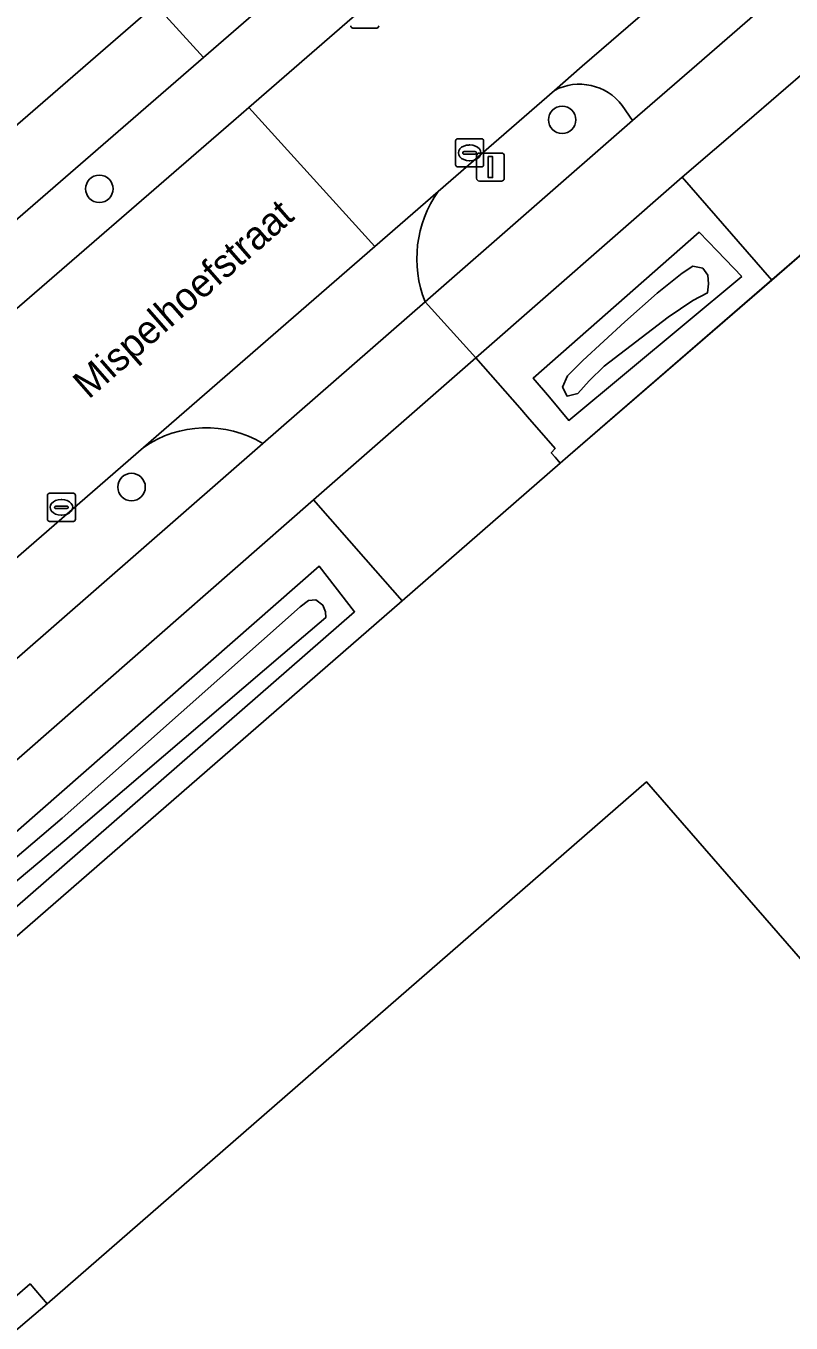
# Model space of a CAD drawing. Extents: x 156141 to 158132, y 385651 to 388333.
# Drawn here: x 156570.49 to 156597.75, y 386888.08 to 386934.27 of the extents above; entities that cross this region are included whole.
import ezdxf

# ---------------------------------------------------------------- set-up
doc = ezdxf.new("R2010")
doc.units = 0
for name, color, linetype in [('IMGEO_Berm_groen', 7, 'Continuous'), ('IMGEO_Boom', 7, 'Continuous'), ('IMGEO_Erf', 7, 'Continuous'), ('IMGEO_Fietspad_gesloten', 7, 'Continuous'), ('IMGEO_Groenvoorziening', 7, 'Continuous'), ('IMGEO_Hek', 7, 'Continuous'), ('IMGEO_Kolk', 7, 'Continuous'), ('IMGEO_Lichtmast', 7, 'Continuous'), ('IMGEO_Oever', 7, 'Continuous'), ('IMGEO_Openbare_ruimte_label', 7, 'Continuous'), ('IMGEO_Pand', 7, 'Continuous'), ('IMGEO_Pand_overbouw', 7, 'Continuous'), ('IMGEO_Rijbaan_lokaal_gesloten', 7, 'Continuous'), ('IMGEO_Rijbaan_lokaal_open', 7, 'Continuous'), ('IMGEO_Waterloop', 7, 'Continuous')]:
    doc.layers.add(name, color=color, linetype=linetype)

msp = doc.modelspace()

# ---------------------------------------------------------------- linework, layer by layer
at = {"layer": 'IMGEO_Berm_groen'}
msp.add_lwpolyline([(156578.429, 386931.366), (156584.359, 386936.515), (156582.78, 386938.315), (156576.815, 386933.146), (156532.37, 386894.634), (156533.965, 386892.782), (156542.199, 386899.938), (156560.328, 386915.699), (156577.884, 386930.893)], close=True, dxfattribs=at)
for points in [[(156589.323, 386931.973), (156585.177, 386928.373)], [(156592.108, 386930.903), (156591.736, 386931.437)], [(156584.717, 386924.449), (156592.108, 386930.903)], [(156548.205, 386892.563), (156578.937, 386919.402)], [(156574.683, 386919.259), (156549.237, 386897.161)]]:
    msp.add_lwpolyline(points, dxfattribs=at)
for centre, radius, start, end in [((156590.211, 386930.271), 1.92, 37.4075, 117.545), ((156588.571, 386925.986), 4.15, 144.886, 201.7417), ((156576.921, 386916.039), 3.921, 59.0516, 124.799)]:
    msp.add_arc(centre, radius, start, end, dxfattribs=at)
at = {"layer": 'IMGEO_Boom'}
for centre in [(156589.598, 386930.924), (156573.109, 386928.467), (156574.257, 386917.849)]:
    msp.add_circle(centre, 0.489, dxfattribs=at)
at = {"layer": 'IMGEO_Erf'}
msp.add_lwpolyline([(156651.128, 386972.023), (156601.597, 386929.14), (156597.069, 386925.22), (156589.805, 386918.931), (156589.532, 386918.694), (156583.893, 386913.793), (156553.079, 386887.01), (156541.121, 386876.586), (156521.047, 386859.086), (156514.467, 386853.349), (156510.617, 386850.009), (156509.404, 386851.42), (156507.703, 386853.398), (156503.3, 386849.53), (156505.031, 386847.528), (156506.198, 386846.177), (156510.785, 386840.87), (156507.066, 386837.556), (156500.596, 386831.732), (156500, 386831.198), (156491.571, 386823.646)], dxfattribs=at)
msp.add_lwpolyline([(156578.998, 386792.742), (156536.648, 386841.452), (156528.398, 386850.929), (156539.01, 386860.157), (156540.506, 386861.457), (156539.644, 386862.468), (156541.875, 386864.404), (156542.756, 386863.396), (156544.258, 386864.709), (156553.863, 386857.558), (156554.405, 386856.904), (156564.643, 386845.132), (156582.749, 386860.855), (156583.794, 386861.763), (156573.533, 386873.547), (156565.273, 386883.021), (156568.324, 386885.629), (156567.989, 386886.001), (156571.25, 386888.765), (156592.606, 386907.35), (156643.504, 386848.886)], close=True, dxfattribs=at)
at = {"layer": 'IMGEO_Fietspad_gesloten'}
for points in [[(156633.634, 386985.932), (156586.015, 386944.463), (156581.136, 386940.239), (156575.112, 386935.021), (156576.815, 386933.146), (156582.78, 386938.315), (156587.706, 386942.532), (156630.724, 386979.99)], [(156639.934, 386972.079), (156623.796, 386958.282), (156620.362, 386955.41), (156596.736, 386934.912), (156594.395, 386932.881), (156592.108, 386930.903), (156584.717, 386924.449), (156586.522, 386922.453), (156593.871, 386928.888), (156596.178, 386930.849), (156598.436, 386932.799), (156641.725, 386970.178)], [(156538.111, 386880.059), (156550.026, 386890.493), (156580.742, 386917.392), (156586.522, 386922.453), (156584.717, 386924.449), (156578.937, 386919.402), (156548.205, 386892.563), (156536.317, 386882.144)]]:
    msp.add_lwpolyline(points, dxfattribs=at)
msp.add_lwpolyline([(156527.655, 386890.556), (156532.37, 386894.634), (156576.815, 386933.146), (156575.112, 386935.021), (156530.069, 386896.004), (156526.123, 386892.626), (156505.841, 386875.055), (156501.161, 386871.018), (156500, 386870.014), (156498.118, 386868.387), (156493.807, 386864.708), (156486.891, 386858.499), (156488.601, 386856.57), (156488.938, 386856.873), (156495.265, 386862.481), (156498.994, 386865.729), (156499.145, 386865.756), (156500.063, 386866.568), (156502.896, 386869.072), (156507.435, 386873.064)], close=True, dxfattribs=at)
at = {"layer": 'IMGEO_Groenvoorziening'}
msp.add_lwpolyline([(156548.555, 386953.619), (156542.644, 386960.844), (156536.4, 386968.352), (156533.608, 386972.166), (156526.591, 386980.435), (156524.337, 386983.087), (156484.391, 386948.01), (156486.162, 386946.33), (156489.804, 386942.873), (156517.635, 386961.628), (156527.955, 386965.366), (156532.292, 386960.323), (156561.896, 386926.176), (156528.865, 386897.414), (156530.069, 386896.004), (156575.112, 386935.021), (156581.136, 386940.239), (156580.507, 386940.959), (156585.398, 386945.175), (156586.015, 386944.463), (156633.634, 386985.932)], dxfattribs=at)
for points in [[(156593.871, 386928.888), (156586.522, 386922.453), (156588.089, 386920.663), (156588.359, 386920.354), (156589.348, 386919.223), (156589.208, 386919.065), (156589.344, 386918.909), (156589.532, 386918.694), (156589.805, 386918.931), (156597.069, 386925.22)], [(156596.002, 386925.351), (156589.834, 386920.221), (156589.142, 386921.046), (156588.57, 386921.728), (156594.477, 386926.919), (156595.118, 386926.26)], [(156580.742, 386917.392), (156550.026, 386890.493), (156551.303, 386889.064), (156552.113, 386888.127), (156552.578, 386887.589), (156553.079, 386887.01), (156583.893, 386913.793), (156582.603, 386915.267)], [(156553.428, 386888.33), (156553.164, 386888.388), (156552.917, 386888.588), (156552.677, 386888.973), (156552.533, 386889.59), (156552.564, 386890.169), (156580.936, 386915.036), (156581.509, 386914.3), (156582.202, 386913.41)]]:
    msp.add_lwpolyline(points, close=True, dxfattribs=at)
at = {"layer": 'IMGEO_Hek'}
for points in [[(156589.532, 386918.694), (156589.805, 386918.931), (156651.128, 386972.023), (156652.016, 386972.784)], [(156583.893, 386913.793), (156589.532, 386918.694)], [(156553.079, 386887.01), (156583.893, 386913.793)]]:
    msp.add_lwpolyline(points, dxfattribs=at)
at = {"layer": 'IMGEO_Kolk'}
for p, q in [((156582.992, 386934.193), (156582.14, 386934.193)), ((156585.799, 386929.322), (156585.799, 386930.174)), ((156585.874, 386930.248), (156586.726, 386930.248)), ((156586.287, 386930.028), (156586.312, 386930.028)), ((156586.8, 386930.174), (156586.8, 386929.322)), ((156586.058, 386929.742), (156586.058, 386929.754)), ((156586.496, 386929.705), (156586.098, 386929.705)), ((156586.101, 386929.791), (156586.499, 386929.791)), ((156586.542, 386929.754), (156586.542, 386929.742)), ((156586.726, 386929.248), (156585.874, 386929.248)), ((156586.31, 386929.468), (156586.285, 386929.468)), ((156571.258, 386916.7), (156571.258, 386917.552)), ((156571.333, 386917.626), (156572.185, 386917.626)), ((156572.259, 386917.552), (156572.259, 386916.7)), ((156571.517, 386917.12), (156571.517, 386917.132)), ((156571.955, 386917.083), (156571.557, 386917.083)), ((156571.56, 386917.169), (156571.958, 386917.169)), ((156571.746, 386917.406), (156571.771, 386917.406)), ((156572.001, 386917.132), (156572.001, 386917.12)), ((156572.185, 386916.626), (156571.333, 386916.626)), ((156571.769, 386916.846), (156571.744, 386916.846))]:
    msp.add_line(p, q, dxfattribs=at)
for points in [[(156582.992, 386934.193), (156582.14, 386934.193)], [(156585.799, 386929.322), (156585.799, 386930.174)], [(156585.874, 386930.248), (156586.726, 386930.248)], [(156586.8, 386930.174), (156586.8, 386929.322)], [(156586.726, 386929.248), (156585.874, 386929.248)], [(156571.258, 386916.7), (156571.258, 386917.552)], [(156571.333, 386917.626), (156572.185, 386917.626)], [(156572.259, 386917.552), (156572.259, 386916.7)], [(156572.185, 386916.626), (156571.333, 386916.626)]]:
    msp.add_lwpolyline(points, dxfattribs=at)
for centre, radius, start, end in [((156582.142, 386934.269), 0.0765, 181.552, 268.448), ((156582.142, 386934.269), 0.0765, 181.552, 268.448), ((156582.99, 386934.269), 0.0765, 271.552, 358.448), ((156582.99, 386934.269), 0.0765, 271.552, 358.448), ((156585.876, 386930.172), 0.0765, 91.552, 178.448), ((156585.876, 386930.172), 0.0765, 91.552, 178.448), ((156586.724, 386930.172), 0.0765, 1.552, 88.448), ((156586.724, 386930.172), 0.0765, 1.552, 88.448), ((156586.098, 386929.751), 0.0403, 85.8775, 175.7526), ((156586.095, 386929.741), 0.0366, 178.938, 274.7102), ((156586.499, 386929.748), 0.043, 264.8664, 352.4533), ((156586.503, 386929.753), 0.0386, 1.7309, 96.639), ((156585.876, 386929.324), 0.0765, 181.552, 268.448), ((156585.876, 386929.324), 0.0765, 181.552, 268.448), ((156586.724, 386929.324), 0.0765, 271.552, 358.448), ((156586.724, 386929.324), 0.0765, 271.552, 358.448), ((156571.335, 386917.55), 0.0765, 91.552, 178.448), ((156571.335, 386917.55), 0.0765, 91.552, 178.448), ((156572.183, 386917.55), 0.0765, 1.552, 88.448), ((156572.183, 386917.55), 0.0765, 1.552, 88.448), ((156571.557, 386917.129), 0.0403, 85.8775, 175.7526), ((156571.554, 386917.119), 0.0366, 178.938, 274.7102), ((156571.958, 386917.126), 0.043, 264.8664, 352.4533), ((156571.962, 386917.131), 0.0386, 1.7309, 96.639), ((156571.335, 386916.702), 0.0765, 181.552, 268.448), ((156571.335, 386916.702), 0.0765, 181.552, 268.448), ((156572.183, 386916.702), 0.0765, 271.552, 358.448), ((156572.183, 386916.702), 0.0765, 271.552, 358.448)]:
    msp.add_arc(centre, radius, start, end, dxfattribs=at)
for centre, major_axis, ratio, start_param, end_param in [((156586.286, 386929.748), (-0.387, 0.002), 0.722429, 4.712389, 7.853982), ((156586.311, 386929.748), (-0.39, 0.002), 0.717154, 1.570796, 4.712389), ((156571.745, 386917.126), (-0.387, 0.002), 0.722429, 4.712389, 7.853982), ((156571.77, 386917.126), (-0.39, 0.002), 0.717154, 1.570796, 4.712389)]:
    msp.add_ellipse(centre, major_axis=major_axis, ratio=ratio, start_param=start_param, end_param=end_param, dxfattribs=at)
at = {"layer": 'IMGEO_Lichtmast'}
for p, q in [((156586.547, 386928.842), (156586.547, 386929.642)), ((156586.547, 386929.642), (156586.547, 386928.842)), ((156586.647, 386929.742), (156587.437, 386929.742)), ((156587.437, 386929.742), (156586.647, 386929.742)), ((156587.537, 386929.642), (156587.537, 386928.842)), ((156587.537, 386928.842), (156587.537, 386929.642)), ((156587.437, 386928.742), (156586.647, 386928.742)), ((156586.647, 386928.742), (156587.437, 386928.742))]:
    msp.add_line(p, q, dxfattribs=at)
msp.add_lwpolyline([(156586.967, 386929.617), (156587.117, 386929.617), (156587.117, 386928.867), (156586.967, 386928.867), (156586.967, 386929.617)], dxfattribs=at)
for centre, start, end in [((156586.647, 386929.642), 90, 180), ((156586.647, 386929.642), 90, 180), ((156587.437, 386929.642), 0, 90), ((156587.437, 386929.642), 360, 90), ((156586.647, 386928.842), 180, 270), ((156586.647, 386928.842), 180, 270), ((156587.437, 386928.842), 270, 0), ((156587.437, 386928.842), 270, 0)]:
    msp.add_arc(centre, 0.1, start, end, dxfattribs=at)
at = {"layer": 'IMGEO_Oever'}
for points in [[(156596.002, 386925.351), (156595.118, 386926.26), (156594.477, 386926.919), (156588.57, 386921.728), (156589.142, 386921.046), (156589.834, 386920.221)], [(156593.874, 386925.459), (156594.247, 386925.71), (156594.605, 386925.637), (156594.783, 386925.398), (156594.814, 386925.079), (156594.771, 386924.761), (156594.253, 386924.494), (156593.373, 386923.9), (156591.097, 386922.155), (156590.554, 386921.627), (156590.15, 386921.185), (156589.773, 386921.09), (156589.613, 386921.404), (156589.791, 386921.814), (156590.335, 386922.353), (156591.836, 386923.729), (156592.987, 386924.755)], [(156552.564, 386890.169), (156552.533, 386889.59), (156552.677, 386888.973), (156552.917, 386888.588), (156553.164, 386888.388), (156553.428, 386888.33), (156582.202, 386913.41), (156581.509, 386914.3), (156580.936, 386915.036)], [(156580.261, 386913.581), (156580.559, 386913.804), (156580.825, 386913.836), (156581.067, 386913.637), (156581.169, 386913.41), (156581.173, 386913.202), (156580.379, 386912.526), (156571.878, 386905.268), (156562.111, 386897.073), (156555.337, 386891), (156553.726, 386889.38), (156553.47, 386889.389), (156553.351, 386889.639), (156553.365, 386889.837), (156558.031, 386894.11), (156562.446, 386898.114), (156571.79, 386906.064)]]:
    msp.add_lwpolyline(points, close=True, dxfattribs=at)
at = {"layer": 'IMGEO_Pand'}
msp.add_lwpolyline([(156578.998, 386792.742), (156643.504, 386848.886), (156592.606, 386907.35), (156571.25, 386888.765), (156567.989, 386886.001), (156568.324, 386885.629), (156565.273, 386883.021), (156573.533, 386873.547), (156583.794, 386861.763), (156582.749, 386860.855), (156564.643, 386845.132), (156554.405, 386856.904), (156553.863, 386857.558), (156544.258, 386864.709), (156542.756, 386863.396), (156541.875, 386864.404), (156539.644, 386862.468), (156540.506, 386861.457), (156539.01, 386860.157), (156528.398, 386850.929), (156536.648, 386841.452)], close=True, dxfattribs=at)
at = {"layer": 'IMGEO_Pand_overbouw'}
msp.add_lwpolyline([(156554.405, 386856.904), (156572.457, 386872.611), (156573.533, 386873.547), (156565.273, 386883.021), (156568.324, 386885.629), (156567.989, 386886.001), (156571.25, 386888.765), (156570.641, 386889.476), (156563.285, 386883.08), (156543.112, 386865.539), (156538.105, 386861.186), (156526.383, 386850.994), (156535.526, 386840.489), (156536.648, 386841.452), (156528.398, 386850.929), (156539.01, 386860.157), (156540.506, 386861.457), (156539.644, 386862.468), (156541.875, 386864.404), (156542.756, 386863.396), (156544.258, 386864.709), (156553.863, 386857.558)], close=True, dxfattribs=at)
at = {"layer": 'IMGEO_Rijbaan_lokaal_gesloten'}
for points in [[(156633.219, 386978.909), (156629.928, 386976.06), (156624.346, 386971.227), (156608.255, 386957.284), (156595.617, 386946.291), (156589.23, 386940.745), (156584.359, 386936.515), (156578.429, 386931.366), (156582.924, 386926.417), (156585.177, 386928.373), (156589.323, 386931.973), (156590.314, 386932.834), (156592.642, 386934.844), (156596.332, 386938.042), (156618.647, 386957.381), (156621.999, 386960.286), (156635.321, 386971.863)], [(156532.275, 386882.472), (156549.237, 386897.161), (156574.683, 386919.259), (156582.924, 386926.417), (156578.429, 386931.366), (156577.884, 386930.893), (156560.328, 386915.699), (156542.199, 386899.938)]]:
    msp.add_lwpolyline(points, dxfattribs=at)
at = {"layer": 'IMGEO_Rijbaan_lokaal_open'}
for points in [[(156596.332, 386938.042), (156592.642, 386934.844), (156590.314, 386932.834), (156589.323, 386931.973)], [(156591.736, 386931.437), (156592.108, 386930.903), (156594.395, 386932.881), (156596.736, 386934.912), (156596.307, 386935.417)], [(156585.177, 386928.373), (156582.924, 386926.417), (156574.683, 386919.259)], [(156578.937, 386919.402), (156584.717, 386924.449)]]:
    msp.add_lwpolyline(points, dxfattribs=at)
for points in [[(156598.436, 386932.799), (156596.178, 386930.849), (156593.871, 386928.888), (156597.069, 386925.22), (156601.597, 386929.14)], [(156589.532, 386918.694), (156589.344, 386918.909), (156589.208, 386919.065), (156589.348, 386919.223), (156588.359, 386920.354), (156588.089, 386920.663), (156586.522, 386922.453), (156580.742, 386917.392), (156582.603, 386915.267), (156583.893, 386913.793)]]:
    msp.add_lwpolyline(points, close=True, dxfattribs=at)
for centre, radius, start, end in [((156590.211, 386930.271), 1.92, 37.4075, 117.545), ((156588.571, 386925.986), 4.15, 144.886, 201.7417), ((156576.921, 386916.039), 3.921, 59.0516, 124.799)]:
    msp.add_arc(centre, radius, start, end, dxfattribs=at)
at = {"layer": 'IMGEO_Waterloop'}
for points in [[(156593.874, 386925.459), (156592.987, 386924.755), (156591.836, 386923.729), (156590.335, 386922.353), (156589.791, 386921.814), (156589.613, 386921.404), (156589.773, 386921.09), (156590.15, 386921.185), (156590.554, 386921.627), (156591.097, 386922.155), (156593.373, 386923.9), (156594.253, 386924.494), (156594.771, 386924.761), (156594.814, 386925.079), (156594.783, 386925.398), (156594.605, 386925.637), (156594.247, 386925.71)], [(156580.261, 386913.581), (156571.79, 386906.064), (156562.446, 386898.114), (156558.031, 386894.11), (156553.365, 386889.837), (156553.351, 386889.639), (156553.47, 386889.389), (156553.726, 386889.38), (156555.337, 386891), (156562.111, 386897.073), (156571.878, 386905.268), (156580.379, 386912.526), (156581.173, 386913.202), (156581.169, 386913.41), (156581.067, 386913.637), (156580.825, 386913.836), (156580.559, 386913.804)]]:
    msp.add_lwpolyline(points, close=True, dxfattribs=at)

# ---------------------------------------------------------------- texts
at = {"layer": 'IMGEO_Openbare_ruimte_label'}
msp.add_text('Mispelhoefstraat', height=1, rotation=41.229, dxfattribs=at).set_placement((156572.728, 386920.95))

doc.saveas('drawing.dxf')
